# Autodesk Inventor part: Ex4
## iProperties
Author: Administrator
Created: 2001-01
Part Number: Ex4
Document SubType Name: Modeling
Designer: Administrator
Control State: 0
Master: False
Checked Out: False
PropertySet Name: Design Tracking Control
Shininess: 0.0
PropertySet Name: _Private Model Information
Density: 0.0
Volumn: 0.0
Area: 0.0
PropertySet Name: Model Information
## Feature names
1. Extrusion1
2. Extrusion2
3. Extrusion3
4. Extrusion4
5. Hole1
6. Hole2
7. Hole3
8. Fillet1
9. Fillet2
10. Fillet3
11. Fillet4
